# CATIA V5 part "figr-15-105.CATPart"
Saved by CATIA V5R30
Part number: Part1
Bounding box of the stored display mesh (mm): x -66.07 to 66.07, y -35.456 to 35.456, z -8 to 1
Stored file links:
  D:\PROJECTS\CATIA V56R 2020\Resources\Parts File\c15_catia_v5_6r2020_prt\figr-15-105.CATPart
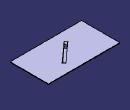
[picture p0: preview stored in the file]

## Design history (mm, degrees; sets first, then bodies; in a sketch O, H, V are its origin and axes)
SheetMetalParameters1: Thickness 1, BendRadius 5, KFactor 0.5 {= log(min(100,max(20*SheetMetalParameters1.BendRadius,SheetMetalParameters1.Thickness)/SheetMetalParameters1.Thickness))/log(100)/2}, ReliefRadialLength 1, ReliefAxialLength 2, MinimumBendRadius 0
Body1 (main body)
  Sketch1 on xy-plane, origin (0, 0, 0), H (1, 0, 0), V (0, 1, 0)
    line L1 (66.07, 35.4565) -> (66.07, -35.4565)
    line L2 (66.07, -35.4565) -> (-66.07, -35.4565)
    line L3 (-66.07, -35.4565) -> (-66.07, 35.4565)
    line L4 (-66.07, 35.4565) -> (66.07, 35.4565)
    vertical: L1 V, L3 V
    horizontal: L2 H, L4 H
    equidistance: L1 L3 O, L2 L4 O
  Wall1: Thickness 1, Profile Sketch1
  Sketch2 on face of Wall1, origin (0, 0, 1), H (1, 0, 0), V (0, 1, 0)
    point P1 (0, 0)
    coincidence: P1 O
  Sketch3 on face of Wall1, origin (0, 0, 1), H (1, 0, 0), V (0, 1, 0)
    point P1 (0, 0)
    reference projected point E1 (0, 0) from Sketch2.P1
    coincidence: E1 P1
  d_Stamp1: Stamp_FilletRadius 2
